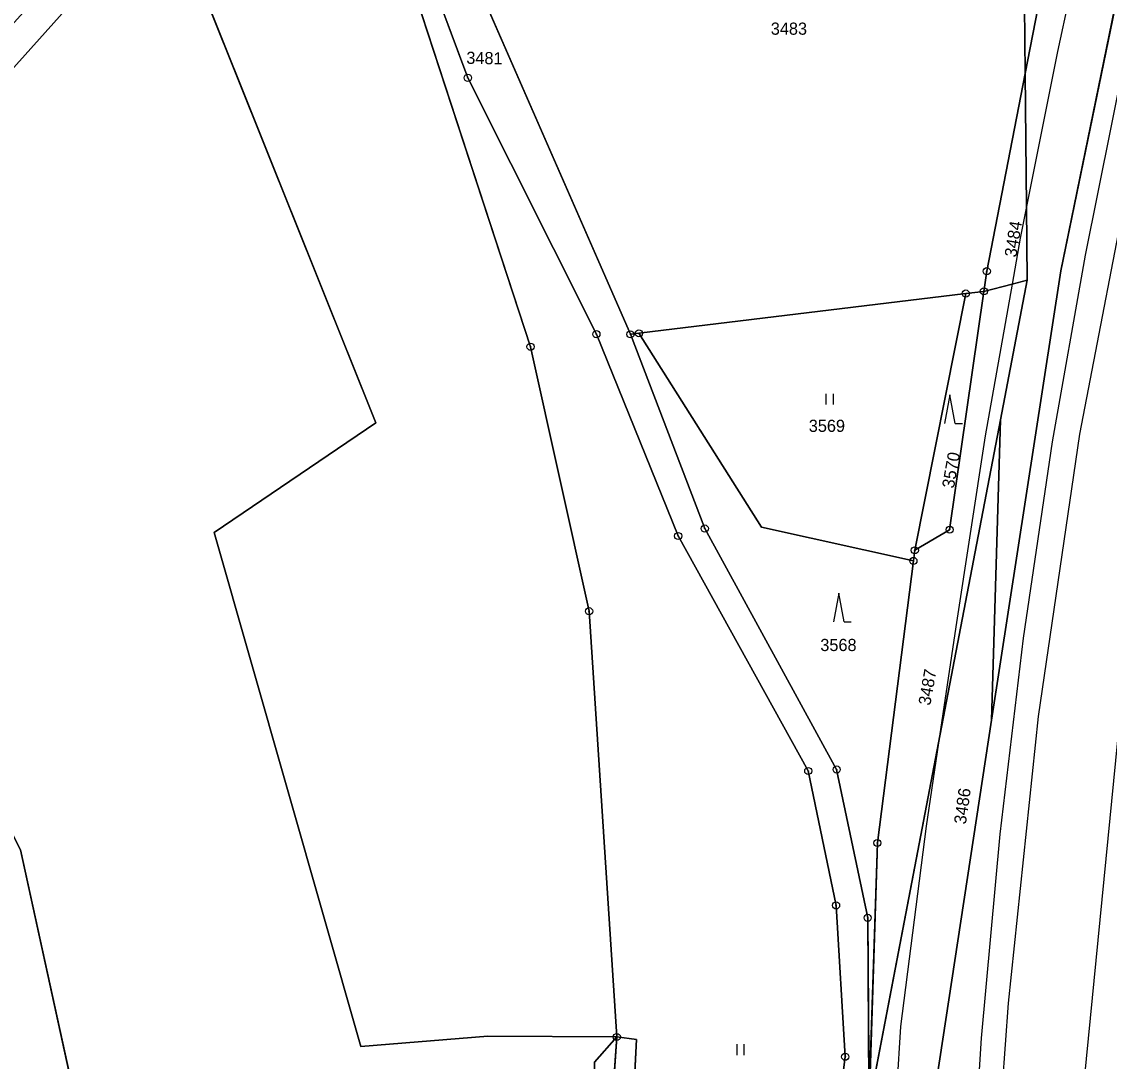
# Model space of a CAD drawing. Extents: x -689422 to -685210, y -987725 to -982160.
# Drawn here: x -687069.9 to -686918.1, y -987436.5 to -987291.4 of the extents above; entities that cross this region are included whole.
import ezdxf

# ---------------------------------------------------------------- set-up
doc = ezdxf.new("R2010")
doc.units = 0
for name, color, linetype in [('KN_Hranice_parcel', 7, 'Continuous'), ('KN_Hranice_parcel_vnitrni_kresba', 7, 'Continuous'), ('KN_Parcelni cisla', 7, 'Continuous'), ('KN_Polygon parcely', 7, 'Continuous'), ('KN_POZEMKY_LESNI POZEMEK', 7, 'Continuous'), ('KN_POZEMKY_OSTATNI PLOCHA', 7, 'Continuous'), ('KN_POZEMKY_TTP', 7, 'Continuous'), ('KN_VYUZITI_16_ostatni plocha_silnice', 7, 'Continuous'), ('KN_VYUZITI_17_ostatni plocha_ostatni komunikace', 7, 'Continuous'), ('KN_VYUZITI_27_ostatni plocha_neplodna puda', 7, 'Continuous'), ('KN_Věcná břemena k části', 7, 'Continuous'), ('KN_Značky bodu BP', 7, 'Continuous'), ('KN_Značky kultur', 7, 'Continuous')]:
    doc.layers.add(name, color=color, linetype=linetype)

msp = doc.modelspace()

# ---------------------------------------------------------------- linework, layer by layer
at = {"layer": 'KN_Hranice_parcel'}
for p, q in [((-686984.94, -987335.07), (-687012.07, -987272.93)), ((-686929.85, -987298.64), (-686929.94, -987289.16)), ((-686935.21, -987326.26), (-686929.85, -987298.64)), ((-686935.61, -987329.07), (-686935.21, -987326.26)), ((-686929.57, -987327.5), (-686933.28, -987347.01)), ((-686983.75, -987334.93), (-686938.14, -987329.38)), ((-686945.26, -987365.22), (-686938.14, -987329.38)), ((-686938.14, -987329.38), (-686935.61, -987329.07)), ((-686984.94, -987335.07), (-686983.75, -987334.93)), ((-686933.28, -987347.01), (-686934.53, -987388.95)), ((-686945.26, -987365.22), (-686945.45, -987366.7)), ((-686934.53, -987388.95), (-686942.18, -987438.97))]:
    msp.add_line(p, q, dxfattribs=at)
for points in [[(-686986.84, -987433.15), (-687004.82, -987433.02), (-687022.56, -987434.48), (-687043.04, -987362.72), (-687020.46, -987347.43), (-687055.2, -987260.69), (-687071.31, -987234.58), (-687077.66, -987221.17), (-687089.53, -987188.12), (-687101.73, -987130.92)], [(-687017.23, -987574.96), (-687027.8, -987570.12), (-687040.5, -987554.3), (-687045.67, -987527.67), (-687046.45, -987508.08), (-687056.87, -987467.32), (-687070.05, -987407.03), (-687091.3, -987364.91), (-687111.64, -987310.66), (-687136.18, -987237.14), (-687149.8, -987184.34)], [(-686896.39, -987191.37), (-686898.12, -987200.55), (-686901.19, -987210.68), (-686924.86, -987326.21), (-686934.53, -987388.95)], [(-686986.84, -987433.15), (-686990.7, -987373.72), (-686998.87, -987336.8), (-687026.9, -987251.12), (-687023.3, -987248.95)], [(-687023.3, -987248.95), (-687017.06, -987273.9), (-687007.63, -987299.27), (-686989.69, -987335.05), (-686978.28, -987363.22), (-686960.12, -987396.02), (-686956.24, -987414.78), (-686954.96, -987435.91), (-686958.92, -987466.99), (-686965.41, -987486.89)], [(-686926.91, -987283.89), (-686928.09, -987289.58), (-686929.85, -987298.64)], [(-686929.57, -987327.5), (-686929.67, -987317.21), (-686929.85, -987298.64)], [(-686935.61, -987329.07), (-686931.69, -987328.05), (-686929.57, -987327.5)], [(-686935.61, -987329.07), (-686940.39, -987362.34), (-686945.26, -987365.22)], [(-686951.64, -987442.68), (-686951.83, -987416.53), (-686956.16, -987395.82), (-686974.56, -987362.18), (-686984.94, -987335.07)], [(-686945.45, -987366.7), (-686966.64, -987362), (-686983.75, -987334.93)], [(-686933.28, -987347.01), (-686941.93, -987392.09), (-686951.64, -987442.68)], [(-686945.45, -987366.7), (-686950.48, -987406.07), (-686951.64, -987442.68)], [(-687017.23, -987574.96), (-687013.38, -987539.2), (-687002.86, -987491.47), (-686990.02, -987445.9), (-686989.93, -987436.67), (-686986.84, -987433.15)], [(-686986.84, -987433.15), (-686987.71, -987445.7), (-687000.92, -987490.88), (-687008.92, -987532.3), (-687015.14, -987575.92)], [(-686986.84, -987433.15), (-686984.08, -987433.52), (-686984.69, -987445.33), (-686994.84, -987487.6), (-686999.53, -987504.44), (-687008.25, -987539.51), (-687011.95, -987574.94)]]:
    msp.add_lwpolyline(points, dxfattribs=at)
at = {"layer": 'KN_Hranice_parcel_vnitrni_kresba'}
for p, q in [((-686919.57, -987268.82), (-686925.36, -987295.59)), ((-686925.36, -987295.59), (-686929.67, -987317.21)), ((-686916.08, -987297.18), (-686921.49, -987324)), ((-686914.68, -987309.48), (-686922.27, -987349)), ((-686929.67, -987317.21), (-686930.56, -987321.67)), ((-686930.56, -987321.67), (-686931.69, -987328.05)), ((-686921.49, -987324), (-686926.07, -987350.06)), ((-686931.69, -987328.05), (-686935.44, -987349.25)), ((-686935.44, -987349.25), (-686939.54, -987375.91)), ((-686922.27, -987349), (-686928.04, -987388.43)), ((-686926.07, -987350.06), (-686930.12, -987377.5)), ((-686939.54, -987375.91), (-686941.93, -987392.09)), ((-686930.12, -987377.5), (-686933.39, -987404.84)), ((-686928.04, -987388.43), (-686932.23, -987428.44)), ((-686916.67, -987388.87), (-686921.6, -987439.05)), ((-686941.93, -987392.09), (-686943.65, -987403.72)), ((-686943.65, -987403.72), (-686947.25, -987431.69)), ((-686933.39, -987404.84), (-686936, -987433.32)), ((-686932.23, -987428.44), (-686933.71, -987448.43)), ((-686947.25, -987431.69), (-686948.64, -987453.99)), ((-686936, -987433.32), (-686937.62, -987459.9))]:
    msp.add_line(p, q, dxfattribs=at)
at = {"layer": 'KN_Polygon parcely'}
for points in [[(-686858.63, -987033.94), (-686876.05, -987102.29), (-686879.29, -987115), (-686880.68, -987119.19), (-686882.17, -987134.31), (-686889.77, -987168.22), (-686890.45, -987171.33), (-686896.39, -987191.37), (-686898.12, -987200.55), (-686901.19, -987210.68), (-686924.86, -987326.21), (-686934.53, -987388.95), (-686942.18, -987438.97)], [(-686989.93, -987436.67), (-686986.84, -987433.15), (-687004.82, -987433.02), (-687022.56, -987434.48), (-687043.04, -987362.72), (-687020.46, -987347.43), (-687055.2, -987260.69), (-687071.31, -987234.58), (-687077.66, -987221.17), (-687089.53, -987188.12), (-687101.73, -987130.92), (-687107.05, -987133.19), (-687128.7, -987141.41), (-687133.81, -987145.13), (-687145.5, -987159.88), (-687149.31, -987169.64), (-687149.8, -987184.34), (-687136.18, -987237.14), (-687111.64, -987310.66), (-687091.3, -987364.91), (-687070.05, -987407.03), (-687056.87, -987467.32)], [(-686951.64, -987442.68), (-686951.83, -987416.53), (-686956.16, -987395.82), (-686974.56, -987362.18), (-686984.94, -987335.07), (-687012.07, -987272.93), (-687020.09, -987245.98), (-687036.16, -987217.77), (-687052.28, -987175.23), (-687058.33, -987146.42), (-687063.04, -987145.76), (-687057.29, -987172.87), (-687040.38, -987219.32), (-687024.26, -987246.11), (-687023.3, -987248.95), (-687017.06, -987273.9), (-687007.63, -987299.27), (-686989.69, -987335.05), (-686978.28, -987363.22), (-686960.12, -987396.02), (-686956.24, -987414.78), (-686954.96, -987435.91), (-686958.92, -987466.99)], [(-687056.87, -987467.32), (-687070.05, -987407.03), (-687091.3, -987364.91), (-687111.64, -987310.66), (-687136.18, -987237.14), (-687149.8, -987184.34), (-687150.58, -987207.6), (-687151.33, -987232.24), (-687149.27, -987248.55), (-687145.23, -987269.43), (-687142.15, -987278.65), (-687144.82, -987285.85), (-687124.48, -987311.79), (-687119.87, -987347.39), (-687097.55, -987394.4), (-687089.79, -987416.24), (-687069.89, -987453.95)]]:
    msp.add_lwpolyline(points, dxfattribs=at)
for points in [[(-686986.84, -987433.15), (-686990.7, -987373.72), (-686998.87, -987336.8), (-687026.9, -987251.12), (-687023.3, -987248.95), (-687024.26, -987246.11), (-687040.38, -987219.32), (-687057.29, -987172.87), (-687063.04, -987145.76), (-687063.59, -987122.98), (-687062.27, -987104.38), (-687065.23, -987104.62), (-687069.67, -987108.38), (-687079.4, -987116.46), (-687101.73, -987130.92), (-687089.53, -987188.12), (-687077.66, -987221.17), (-687071.31, -987234.58), (-687055.2, -987260.69), (-687020.46, -987347.43), (-687043.04, -987362.72), (-687022.56, -987434.48), (-687004.82, -987433.02)], [(-686928.09, -987289.58), (-686929.85, -987298.64), (-686929.67, -987317.21), (-686929.57, -987327.5), (-686933.28, -987347.01), (-686934.53, -987388.95), (-686924.86, -987326.21), (-686901.19, -987210.68), (-686898.12, -987200.55), (-686896.39, -987191.37), (-686900.6, -987187.59), (-686907.28, -987181.6), (-686910.39, -987199.89), (-686912.76, -987213.81), (-686919.92, -987250.19), (-686924.17, -987270.69), (-686926.91, -987283.89)], [(-686932.95, -987239.68), (-686973.34, -987256.66), (-687012.07, -987272.93), (-686984.94, -987335.07), (-686983.75, -987334.93), (-686938.14, -987329.38), (-686935.61, -987329.07), (-686935.21, -987326.26), (-686929.85, -987298.64), (-686929.94, -987289.16)], [(-687011.95, -987574.94), (-686998.76, -987569.23), (-686977.57, -987523.3), (-686970.04, -987494.64), (-686965.41, -987486.89), (-686958.92, -987466.99), (-686954.96, -987435.91), (-686956.24, -987414.78), (-686960.12, -987396.02), (-686978.28, -987363.22), (-686989.69, -987335.05), (-687007.63, -987299.27), (-687017.06, -987273.9), (-687023.3, -987248.95), (-687026.9, -987251.12), (-686998.87, -987336.8), (-686990.7, -987373.72), (-686986.84, -987433.15), (-686984.08, -987433.52), (-686984.69, -987445.33), (-686994.84, -987487.6), (-686999.53, -987504.44), (-687008.25, -987539.51)], [(-686926.91, -987283.89), (-686929.94, -987289.16), (-686929.85, -987298.64), (-686928.09, -987289.58)], [(-686929.57, -987327.5), (-686929.67, -987317.21), (-686929.85, -987298.64), (-686935.21, -987326.26), (-686935.61, -987329.07), (-686931.69, -987328.05)], [(-686945.45, -987366.7), (-686950.48, -987406.07), (-686951.64, -987442.68), (-686941.93, -987392.09), (-686933.28, -987347.01), (-686929.57, -987327.5), (-686931.69, -987328.05), (-686935.61, -987329.07), (-686940.39, -987362.34), (-686945.26, -987365.22)], [(-686938.14, -987329.38), (-686983.75, -987334.93), (-686966.64, -987362), (-686945.45, -987366.7), (-686945.26, -987365.22)], [(-686935.61, -987329.07), (-686938.14, -987329.38), (-686945.26, -987365.22), (-686940.39, -987362.34)], [(-686966.64, -987362), (-686983.75, -987334.93), (-686984.94, -987335.07), (-686974.56, -987362.18), (-686956.16, -987395.82), (-686951.83, -987416.53), (-686951.64, -987442.68), (-686950.48, -987406.07), (-686945.45, -987366.7)], [(-686941.93, -987392.09), (-686951.64, -987442.68), (-686952.3, -987445.74), (-686956.75, -987472.85), (-686948.64, -987453.99), (-686942.18, -987438.97), (-686934.53, -987388.95), (-686933.28, -987347.01)], [(-687017.23, -987574.96), (-687015.14, -987575.92), (-687008.92, -987532.3), (-687000.92, -987490.88), (-686987.71, -987445.7), (-686986.84, -987433.15), (-686989.93, -987436.67), (-686990.02, -987445.9), (-687002.86, -987491.47), (-687013.38, -987539.2)], [(-687011.95, -987574.94), (-687008.25, -987539.51), (-686999.53, -987504.44), (-686994.84, -987487.6), (-686984.69, -987445.33), (-686984.08, -987433.52), (-686986.84, -987433.15), (-686987.71, -987445.7), (-687000.92, -987490.88), (-687008.92, -987532.3), (-687015.14, -987575.92)]]:
    msp.add_lwpolyline(points, close=True, dxfattribs=at)
at = {"layer": 'KN_POZEMKY_LESNI POZEMEK'}
for p, q in [((-686945.26, -987365.22), (-686938.14, -987329.38)), ((-686935.61, -987329.07), (-686940.39, -987362.34)), ((-686938.14, -987329.38), (-686935.61, -987329.07)), ((-686984.94, -987335.07), (-686983.75, -987334.93)), ((-686974.56, -987362.18), (-686984.94, -987335.07)), ((-686983.75, -987334.93), (-686966.64, -987362)), ((-686966.64, -987362), (-686945.45, -987366.7)), ((-686956.16, -987395.82), (-686974.56, -987362.18)), ((-686940.39, -987362.34), (-686945.26, -987365.22)), ((-686945.45, -987366.7), (-686950.48, -987406.07)), ((-686951.83, -987416.53), (-686956.16, -987395.82)), ((-686950.48, -987406.07), (-686951.64, -987442.68)), ((-686951.64, -987442.68), (-686951.83, -987416.53))]:
    msp.add_line(p, q, dxfattribs=at)
at = {"layer": 'KN_POZEMKY_OSTATNI PLOCHA'}
for p, q in [((-686901.19, -987210.68), (-686924.86, -987326.21)), ((-686924.86, -987326.21), (-686901.19, -987210.68)), ((-687007.63, -987299.27), (-687017.06, -987273.9)), ((-687012.07, -987272.93), (-686984.94, -987335.07)), ((-686929.85, -987298.64), (-686928.09, -987289.58)), ((-686989.69, -987335.05), (-687007.63, -987299.27)), ((-686935.21, -987326.26), (-686929.85, -987298.64)), ((-686929.85, -987298.64), (-686929.67, -987317.21)), ((-686929.67, -987317.21), (-686929.85, -987298.64)), ((-686929.67, -987317.21), (-686929.57, -987327.5)), ((-686929.57, -987327.5), (-686929.67, -987317.21)), ((-686935.61, -987329.07), (-686935.21, -987326.26)), ((-686924.86, -987326.21), (-686934.53, -987388.95)), ((-686934.53, -987388.95), (-686924.86, -987326.21)), ((-686931.69, -987328.05), (-686935.61, -987329.07)), ((-686935.61, -987329.07), (-686931.69, -987328.05)), ((-686933.28, -987347.01), (-686929.57, -987327.5)), ((-686929.57, -987327.5), (-686933.28, -987347.01)), ((-686929.57, -987327.5), (-686931.69, -987328.05)), ((-686931.69, -987328.05), (-686929.57, -987327.5)), ((-686940.39, -987362.34), (-686935.61, -987329.07)), ((-686978.28, -987363.22), (-686989.69, -987335.05)), ((-686984.94, -987335.07), (-686974.56, -987362.18)), ((-686941.93, -987392.09), (-686933.28, -987347.01)), ((-686933.28, -987347.01), (-686941.93, -987392.09)), ((-686934.53, -987388.95), (-686933.28, -987347.01)), ((-686933.28, -987347.01), (-686934.53, -987388.95)), ((-686960.12, -987396.02), (-686978.28, -987363.22)), ((-686974.56, -987362.18), (-686956.16, -987395.82)), ((-686945.26, -987365.22), (-686940.39, -987362.34)), ((-686945.45, -987366.7), (-686945.26, -987365.22)), ((-686950.48, -987406.07), (-686945.45, -987366.7)), ((-686934.53, -987388.95), (-686942.18, -987438.97)), ((-686942.18, -987438.97), (-686934.53, -987388.95)), ((-686951.64, -987442.68), (-686941.93, -987392.09)), ((-686941.93, -987392.09), (-686951.64, -987442.68)), ((-686956.24, -987414.78), (-686960.12, -987396.02)), ((-686956.16, -987395.82), (-686951.83, -987416.53)), ((-686951.64, -987442.68), (-686950.48, -987406.07)), ((-686954.96, -987435.91), (-686956.24, -987414.78)), ((-686951.83, -987416.53), (-686951.64, -987442.68)), ((-686989.93, -987436.67), (-686986.84, -987433.15)), ((-686986.84, -987433.15), (-686987.71, -987445.7)), ((-686987.71, -987445.7), (-686986.84, -987433.15)), ((-686986.84, -987433.15), (-686984.08, -987433.52)), ((-686984.08, -987433.52), (-686984.69, -987445.33)), ((-686958.92, -987466.99), (-686954.96, -987435.91))]:
    msp.add_line(p, q, dxfattribs=at)
at = {"layer": 'KN_POZEMKY_TTP'}
for p, q in [((-687026.9, -987251.12), (-686998.87, -987336.8)), ((-686998.87, -987336.8), (-687026.9, -987251.12)), ((-687020.46, -987347.43), (-687055.2, -987260.69)), ((-687055.2, -987260.69), (-687020.46, -987347.43)), ((-687017.06, -987273.9), (-687007.63, -987299.27)), ((-686984.94, -987335.07), (-687012.07, -987272.93)), ((-686929.94, -987289.16), (-686929.85, -987298.64)), ((-686929.85, -987298.64), (-686929.94, -987289.16)), ((-686928.09, -987289.58), (-686929.85, -987298.64)), ((-687007.63, -987299.27), (-686989.69, -987335.05)), ((-686929.85, -987298.64), (-686935.21, -987326.26)), ((-686935.21, -987326.26), (-686935.61, -987329.07)), ((-686938.14, -987329.38), (-686983.75, -987334.93)), ((-686983.75, -987334.93), (-686938.14, -987329.38)), ((-686938.14, -987329.38), (-686945.26, -987365.22)), ((-686935.61, -987329.07), (-686938.14, -987329.38)), ((-686989.69, -987335.05), (-686978.28, -987363.22)), ((-686983.75, -987334.93), (-686984.94, -987335.07)), ((-686966.64, -987362), (-686983.75, -987334.93)), ((-686998.87, -987336.8), (-686990.7, -987373.72)), ((-686990.7, -987373.72), (-686998.87, -987336.8)), ((-687043.04, -987362.72), (-687020.46, -987347.43)), ((-687020.46, -987347.43), (-687043.04, -987362.72)), ((-686945.45, -987366.7), (-686966.64, -987362)), ((-687022.56, -987434.48), (-687043.04, -987362.72)), ((-687043.04, -987362.72), (-687022.56, -987434.48)), ((-686978.28, -987363.22), (-686960.12, -987396.02)), ((-686945.26, -987365.22), (-686945.45, -987366.7)), ((-686990.7, -987373.72), (-686986.84, -987433.15)), ((-686986.84, -987433.15), (-686990.7, -987373.72)), ((-686960.12, -987396.02), (-686956.24, -987414.78)), ((-687056.87, -987467.32), (-687070.05, -987407.03)), ((-687070.05, -987407.03), (-687056.87, -987467.32)), ((-686956.24, -987414.78), (-686954.96, -987435.91)), ((-687004.82, -987433.02), (-687022.56, -987434.48)), ((-687022.56, -987434.48), (-687004.82, -987433.02)), ((-686986.84, -987433.15), (-687004.82, -987433.02)), ((-687004.82, -987433.02), (-686986.84, -987433.15)), ((-686986.84, -987433.15), (-686989.93, -987436.67)), ((-686984.08, -987433.52), (-686986.84, -987433.15)), ((-686984.69, -987445.33), (-686984.08, -987433.52)), ((-686954.96, -987435.91), (-686958.92, -987466.99))]:
    msp.add_line(p, q, dxfattribs=at)
at = {"layer": 'KN_VYUZITI_16_ostatni plocha_silnice'}
for p, q in [((-686901.19, -987210.68), (-686924.86, -987326.21)), ((-686924.86, -987326.21), (-686901.19, -987210.68)), ((-686929.85, -987298.64), (-686928.09, -987289.58)), ((-686935.21, -987326.26), (-686929.85, -987298.64)), ((-686929.85, -987298.64), (-686929.67, -987317.21)), ((-686929.67, -987317.21), (-686929.85, -987298.64)), ((-686929.67, -987317.21), (-686929.57, -987327.5)), ((-686929.57, -987327.5), (-686929.67, -987317.21)), ((-686935.61, -987329.07), (-686935.21, -987326.26)), ((-686924.86, -987326.21), (-686934.53, -987388.95)), ((-686934.53, -987388.95), (-686924.86, -987326.21)), ((-686931.69, -987328.05), (-686935.61, -987329.07)), ((-686935.61, -987329.07), (-686931.69, -987328.05)), ((-686933.28, -987347.01), (-686929.57, -987327.5)), ((-686929.57, -987327.5), (-686933.28, -987347.01)), ((-686929.57, -987327.5), (-686931.69, -987328.05)), ((-686931.69, -987328.05), (-686929.57, -987327.5)), ((-686940.39, -987362.34), (-686935.61, -987329.07)), ((-686941.93, -987392.09), (-686933.28, -987347.01)), ((-686933.28, -987347.01), (-686941.93, -987392.09)), ((-686934.53, -987388.95), (-686933.28, -987347.01)), ((-686933.28, -987347.01), (-686934.53, -987388.95)), ((-686945.26, -987365.22), (-686940.39, -987362.34)), ((-686945.45, -987366.7), (-686945.26, -987365.22)), ((-686950.48, -987406.07), (-686945.45, -987366.7)), ((-686934.53, -987388.95), (-686942.18, -987438.97)), ((-686942.18, -987438.97), (-686934.53, -987388.95)), ((-686951.64, -987442.68), (-686941.93, -987392.09)), ((-686941.93, -987392.09), (-686951.64, -987442.68)), ((-686951.64, -987442.68), (-686950.48, -987406.07))]:
    msp.add_line(p, q, dxfattribs=at)
at = {"layer": 'KN_VYUZITI_17_ostatni plocha_ostatni komunikace'}
for p, q in [((-687007.63, -987299.27), (-687017.06, -987273.9)), ((-687012.07, -987272.93), (-686984.94, -987335.07)), ((-686989.69, -987335.05), (-687007.63, -987299.27)), ((-686978.28, -987363.22), (-686989.69, -987335.05)), ((-686984.94, -987335.07), (-686974.56, -987362.18)), ((-686960.12, -987396.02), (-686978.28, -987363.22)), ((-686974.56, -987362.18), (-686956.16, -987395.82)), ((-686956.24, -987414.78), (-686960.12, -987396.02)), ((-686956.16, -987395.82), (-686951.83, -987416.53)), ((-686954.96, -987435.91), (-686956.24, -987414.78)), ((-686951.83, -987416.53), (-686951.64, -987442.68)), ((-686958.92, -987466.99), (-686954.96, -987435.91))]:
    msp.add_line(p, q, dxfattribs=at)
at = {"layer": 'KN_VYUZITI_27_ostatni plocha_neplodna puda'}
for p, q in [((-686989.93, -987436.67), (-686986.84, -987433.15)), ((-686986.84, -987433.15), (-686987.71, -987445.7)), ((-686987.71, -987445.7), (-686986.84, -987433.15)), ((-686986.84, -987433.15), (-686984.08, -987433.52)), ((-686984.08, -987433.52), (-686984.69, -987445.33))]:
    msp.add_line(p, q, dxfattribs=at)
at = {"layer": 'KN_Věcná břemena k části'}
msp.add_lwpolyline([(-687104.74, -987329.05), (-687120.04, -987346.04), (-687119.87, -987347.39), (-687118.33, -987350.62), (-687103.05, -987333.57), (-687049.81, -987274.15), (-687051.5, -987269.93)], close=True, dxfattribs=at)
at = {"layer": 'KN_Značky bodu BP'}
for centre, radius in [((-687007.63, -987299.27), 0.5), ((-687007.63, -987299.27), 0.0303), ((-686935.21, -987326.26), 0.5), ((-686935.21, -987326.26), 0.0303), ((-686935.61, -987329.07), 0.5), ((-686938.14, -987329.38), 0.5), ((-686938.14, -987329.38), 0.0303), ((-686935.61, -987329.07), 0.0303), ((-686989.69, -987335.05), 0.5), ((-686984.94, -987335.07), 0.5), ((-686983.75, -987334.93), 0.5), ((-686989.69, -987335.05), 0.0303), ((-686984.94, -987335.07), 0.0303), ((-686983.75, -987334.93), 0.0303), ((-686998.87, -987336.8), 0.5), ((-686998.87, -987336.8), 0.0303), ((-686974.56, -987362.18), 0.5), ((-686940.39, -987362.34), 0.5), ((-686978.28, -987363.22), 0.5), ((-686978.28, -987363.22), 0.0303), ((-686974.56, -987362.18), 0.0303), ((-686940.39, -987362.34), 0.0303), ((-686945.26, -987365.22), 0.5), ((-686945.45, -987366.7), 0.5), ((-686945.26, -987365.22), 0.0303), ((-686945.45, -987366.7), 0.0303), ((-686990.7, -987373.72), 0.5), ((-686990.7, -987373.72), 0.0303), ((-686956.16, -987395.82), 0.5), ((-686960.12, -987396.02), 0.5), ((-686960.12, -987396.02), 0.0303), ((-686956.16, -987395.82), 0.0303), ((-686950.48, -987406.07), 0.5), ((-686950.48, -987406.07), 0.0303), ((-686956.24, -987414.78), 0.5), ((-686956.24, -987414.78), 0.0303), ((-686951.83, -987416.53), 0.5), ((-686951.83, -987416.53), 0.0303), ((-686986.84, -987433.15), 0.5), ((-686986.84, -987433.15), 0.0303), ((-686954.96, -987435.91), 0.5), ((-686954.96, -987435.91), 0.0303)]:
    msp.add_circle(centre, radius, dxfattribs=at)
at = {"layer": 'KN_Značky kultur'}
for p, q in [((-686957.62, -987344.87), (-686957.62, -987343.37)), ((-686956.62, -987344.87), (-686956.62, -987343.37)), ((-686940.35, -987343.52), (-686941.1, -987347.52)), ((-686939.6, -987347.52), (-686940.35, -987343.52)), ((-686939.6, -987347.52), (-686938.6, -987347.52)), ((-686955.87, -987371.21), (-686956.62, -987375.21)), ((-686955.12, -987375.21), (-686955.87, -987371.21)), ((-686955.12, -987375.21), (-686954.12, -987375.21)), ((-686970.05, -987435.67), (-686970.05, -987434.17)), ((-686969.05, -987435.67), (-686969.05, -987434.17))]:
    msp.add_line(p, q, dxfattribs=at)

# ---------------------------------------------------------------- texts
at = {"layer": 'KN_Parcelni cisla'}
for s, p in [('3483', (-686965.35, -987293.25)), ('3569', (-686960.05, -987348.69)), ('3568', (-686958.44, -987379.28))]:
    msp.add_text(s, height=1.7, dxfattribs=at).set_placement(p)
for s, rotation, p in [('3481', 359, (-687007.85, -987297.31)), ('3484', 81, (-686931.08, -987324.39)), ('3570', 80, (-686939.8, -987356.66)), ('3487', 80, (-686943.1, -987386.96)), ('3486', 82, (-686938.13, -987403.54))]:
    msp.add_text(s, height=1.7, rotation=rotation, dxfattribs=at).set_placement(p)

doc.saveas('drawing.dxf')
